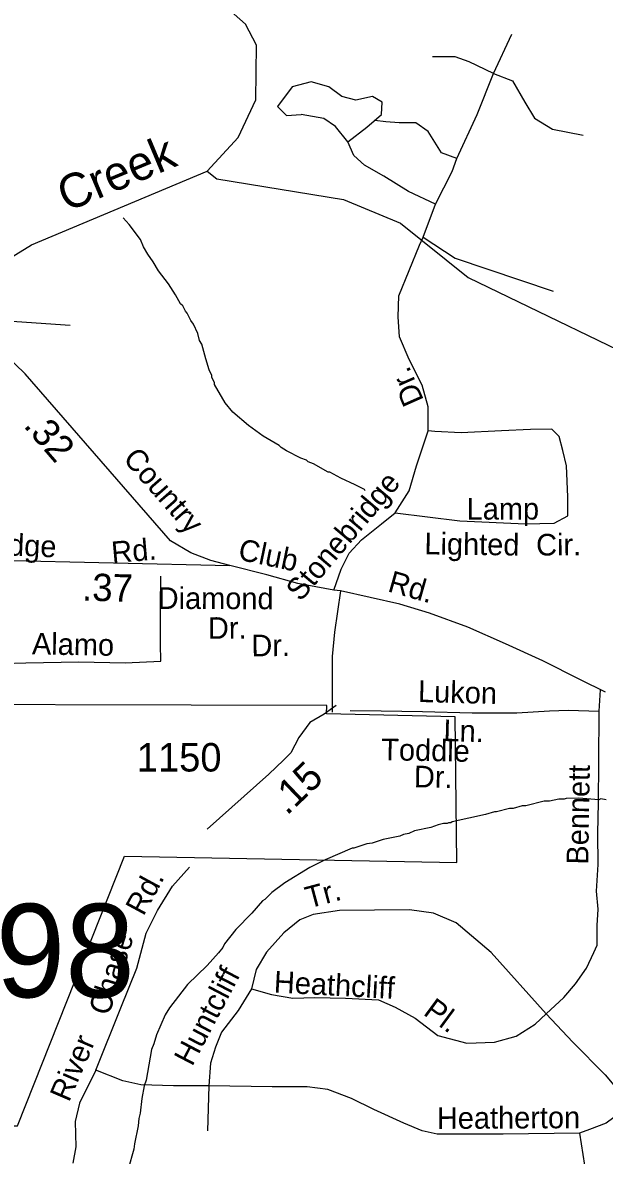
# Model space of a CAD drawing. Extents: x 1547597 to 1699558, y 810033 to 920809.
# Drawn here: x 1597107 to 1599658, y 851025 to 855999 of the extents above; entities that cross this region are included whole.
import ezdxf

# ---------------------------------------------------------------- set-up
doc = ezdxf.new("R2010")
doc.units = 0
for name, color, linetype in [('Exist Boundary Political City Limit New', 7, 'Continuous'), ('Exist Hydrographic Creek Single Shore', 7, 'Continuous'), ('Exist Hydrographic Creek Single Shore Label', 7, 'Continuous'), ('Exist Hydrographic Misc Water Feature', 7, 'Continuous'), ('Exist Road Non-System Type 51', 7, 'Continuous'), ('Exist Road Non-System Type 51 Label', 7, 'Continuous'), ('Exist Road Secondary Mileage Hundredths English Label', 7, 'Continuous'), ('Exist Road Secondary Structure Standard Bridge CELL', 7, 'Continuous'), ('Exist Road Secondary Structure Standard Bridge Number Label', 7, 'Continuous'), ('Exist Road Secondary Type 51 Attributed', 7, 'Continuous'), ('Exist Road Secondary Type 51 Label', 7, 'Continuous'), ('Exist Road Secondary Type 51 Number Label', 7, 'Continuous'), ('Map Preparation Boundary City Limit Buffer Line', 7, 'Continuous')]:
    doc.layers.add(name, color=color, linetype=linetype)

msp = doc.modelspace()

# ---------------------------------------------------------------- linework, layer by layer
at = {"layer": 'Exist Boundary Political City Limit New'}
msp.add_lwpolyline([(1598966.2, 848889), (1598696.7, 848933.6), (1598735.8, 849260.4), (1597051.5, 849266), (1596744.3, 849248.9), (1596741.6, 849203.1), (1596587.6, 849194.5), (1596790.6, 850274.8), (1596971.2, 851155.7), (1597083.9, 851155.7), (1597552.8, 852338.7), (1599010.8, 852311.7), (1599004, 852951.6), (1598440.1, 852963.6), (1598441.2, 853000.9), (1596057.5, 853006.4)], dxfattribs=at)
at = {"layer": 'Exist Hydrographic Creek Single Shore'}
for points in [[(1597916.6, 855346.8), (1598051.6, 855495), (1598128.7, 855660.9), (1598132.7, 855900.5), (1598083.7, 855993.4), (1597959.6, 856104.2), (1597769.6, 856200), (1597613.6, 856400.1), (1597549.6, 856634.5), (1597500.6, 856710.9), (1597454.7, 856961.4), (1597490.7, 857151.1), (1597755.1, 857446.8), (1598364.4, 858096.9), (1598493.9, 858519.8), (1598638.6, 858913.6)], [(1596005.6, 853287.9), (1596117.6, 853594.1), (1596743.8, 854808.1), (1596918.7, 854884.4), (1597145.7, 855024.3), (1597916.6, 855346.8)]]:
    msp.add_lwpolyline(points, dxfattribs=at)
at = {"layer": 'Exist Hydrographic Misc Water Feature'}
for points in [[(1597916.6, 855346.8), (1597957.7, 855313.1), (1598514.6, 855223), (1598763.6, 855119.5), (1599060.6, 854880.4), (1599980.6, 854435), (1600204.6, 854374.6), (1600804.6, 854382.2), (1601163.6, 854427.4), (1601549.7, 854580.4), (1602405.6, 854986.5), (1603296.7, 855565.9), (1603514.7, 855656.7), (1603614.6, 855661.2)], [(1598609.3, 853943), (1598605.4, 853949), (1598565.7, 853969.5), (1598502.2, 853998.5), (1598454.6, 854025.1), (1598446.6, 854025.2), (1598383.1, 854062.1), (1598359.3, 854070.4), (1598351.4, 854078.5), (1598327.5, 854086.9), (1598264, 854119.7), (1598240.1, 854134.1), (1598232.3, 854142.2), (1598160.9, 854183.2), (1598097.6, 854230.1), (1598028.4, 854289), (1597995, 854329.5), (1597948.1, 854410.1), (1597948.2, 854418.1), (1597936.5, 854442.2), (1597936.6, 854450.2), (1597925, 854474.4), (1597909.7, 854522.6), (1597892.6, 854586.9), (1597882.8, 854602.9), (1597875.2, 854635), (1597855.7, 854675.3), (1597844, 854691.5), (1597828.5, 854723.7), (1597820.6, 854731.8), (1597808.9, 854756), (1597799.1, 854764.1), (1597777.6, 854804.4), (1597746.3, 854852.8), (1597703.1, 854909.4), (1597679.6, 854949.7), (1597656, 854982), (1597636.5, 855014.3), (1597623, 855046.5), (1597573.9, 855113.2), (1597547.8, 855142.6)], [(1599666.3, 852586.5), (1599642.3, 852590.8), (1599634.3, 852586.9), (1599546.4, 852594.2), (1599490.4, 852593), (1599482.3, 852589.1), (1599458.4, 852589.4), (1599418.2, 852580), (1599394.3, 852580.3), (1599314.1, 852559.5), (1599298.1, 852559.7), (1599257.9, 852548.2), (1599242, 852548.4), (1599185.8, 852533.2), (1599175.8, 852533.4), (1599137.6, 852521.9), (1598991.3, 852489.9), (1598985.3, 852486), (1598975.2, 852486.1), (1598969.2, 852482.3), (1598953.2, 852482.5), (1598929.2, 852476.8), (1598897, 852465.3), (1598824.8, 852450.3), (1598800.7, 852438.6), (1598776.6, 852434.9), (1598760.5, 852427.2), (1598688.4, 852412.2), (1598640.2, 852396.8), (1598616.2, 852393.2), (1598560, 852374), (1598552, 852374.1), (1598433.4, 852323.7), (1598366.9, 852288.7), (1598256, 852222.2), (1598199.5, 852179.1), (1598169.1, 852149.5), (1598159, 852143.6), (1598112.3, 852088.3), (1598041.4, 852017.3), (1597992.5, 851954), (1597984.3, 851938.1), (1597966.1, 851914.4), (1597915.3, 851859.1), (1597830.2, 851776.3), (1597750.9, 851673.4), (1597732.4, 851641.7), (1597693.2, 851554.2), (1597682.7, 851514.4), (1597672.4, 851490.6), (1597648.5, 851354.9), (1597640.2, 851331), (1597629.5, 851275.2), (1597622.6, 851211.3), (1597616.2, 851187.4), (1597613.9, 851155.5), (1597596.8, 851075.7), (1597594.4, 851051.8), (1597569.3, 850964.1)]]:
    msp.add_lwpolyline(points, dxfattribs=at)
at = {"layer": 'Exist Road Non-System Type 51'}
msp.add_line((1599635.2, 852975.4), (1599641.8, 853069.4), dxfattribs=at)
for points in [[(1599172.4, 855776.7), (1599253, 855948.7)], [(1599172.4, 855776.7), (1599065, 855827.7), (1599003.2, 855849.3), (1598903.8, 855849.3)], [(1599011.3, 855403), (1599099.9, 855596.6), (1599172.4, 855776.7)], [(1599172.4, 855776.7), (1599255.7, 855744.4), (1599309.4, 855650.3), (1599352.4, 855580.4), (1599430.3, 855532.1), (1599564.6, 855505.2)], [(1598533.2, 855475.6), (1598616.4, 855540.1), (1598680.9, 855596.6), (1598683.6, 855650.3), (1598640.6, 855674.5), (1598568.1, 855658.4), (1598506.3, 855674.5), (1598449.9, 855717.5), (1598372, 855739), (1598288.7, 855717.5), (1598224.3, 855631.5), (1598264.6, 855591.2), (1598329, 855596.6)], [(1598533.2, 855475.6), (1598479.4, 855542.8), (1598428.4, 855577.8), (1598329, 855596.6)], [(1599011.3, 855403), (1598944.1, 855427.2), (1598885, 855521.3), (1598831.3, 855558.9), (1598758.8, 855558.9), (1598699.7, 855564.3), (1598651.3, 855569.7)], [(1598917.5, 855202.7), (1598799.1, 855257.9), (1598691.6, 855325.1), (1598605.7, 855373.5), (1598560, 855416.5), (1598533.2, 855475.6)], [(1598917.5, 855202.7), (1598990, 855345.1), (1599011.3, 855403)], [(1598863.7, 855057.5), (1598917.5, 855202.7)], [(1598885.3, 854206.8), (1598885.2, 854312.9), (1598858.4, 854407), (1598802, 854519.9), (1598759, 854619.4), (1598753.6, 854708.1), (1598756.3, 854799.5), (1598847.6, 855022.6), (1598863.7, 855057.5)], [(1598863.7, 855057.5), (1599003.2, 854964.9), (1599433, 854819.7)], [(1598740.3, 853846.6), (1599025, 853811.6), (1599312.4, 853798.2), (1599438.6, 853800.9), (1599497.7, 853833.1), (1599497.7, 853916.4), (1599492.4, 854053.5), (1599476.2, 854120.7), (1599460.1, 854182.6), (1599427.9, 854214.8), (1599333.9, 854212.1), (1599207.6, 854206.8), (1599030.4, 854198.7), (1598914.9, 854204.1), (1598885.3, 854206.8)], [(1598740.3, 853846.6), (1598802.1, 853943.3), (1598834.3, 854053.5), (1598885.3, 854206.8)], [(1598471.7, 853507.9), (1598503.9, 853599.3), (1598538.8, 853669.1), (1598592.6, 853728.3), (1598681.2, 853798.2), (1598740.3, 853846.6)], [(1597712.1, 853195.5), (1597711.4, 853271.5), (1597710.6, 853437.4), (1597712.9, 853569.4)], [(1598501, 853503.6), (1598474.1, 853323.1), (1598464.4, 853215.8)], [(1596622.8, 853179.5), (1596724.9, 853179.7), (1596916.6, 853182.2), (1597120.4, 853188.4), (1597352.4, 853192.1), (1597556.1, 853188.4), (1597712.1, 853195.5)], [(1598464.4, 853215.8), (1598464.4, 852971.8)], [(1598542.7, 852979.1), (1598679, 852977.9), (1598860.6, 852974.4), (1599078.2, 852968.4), (1599274.1, 852968.9), (1599417.5, 852976.7), (1599499.6, 852979.9), (1599635.2, 852975.4)], [(1599402.5, 851647.4), (1599480.5, 851718.2), (1599531.6, 851777.9), (1599579.3, 851847.3), (1599612.5, 851916.7), (1599626.7, 851948.6), (1599627, 852034.5), (1599630.5, 852106.3), (1599624.2, 852185.3), (1599631.5, 852302.4), (1599630.3, 852439.1), (1599632.7, 852574.9), (1599634, 852751.2), (1599635.2, 852975.4)], [(1597427.1, 851399), (1597536.8, 851673.7), (1597607.5, 851846.9), (1597648.9, 852000.6), (1597697.7, 852100.6), (1597763.5, 852208), (1597839.1, 852290.9)], [(1599402.5, 851647.4), (1599161.6, 851915.4), (1599008.1, 852047.1), (1598908.1, 852088.6), (1598803.3, 852103.2), (1598496.1, 852100.8), (1598381.6, 852083.7), (1598323.1, 852059.3), (1598252.4, 852003.2), (1598176.8, 851917.8), (1598130.5, 851842.2), (1598111, 851756.8)], [(1598111, 851756.8), (1598052.5, 851661.7), (1597979.4, 851566.5), (1597952.6, 851500.7), (1597930.6, 851429.9), (1597923.3, 851329.9)], [(1598111, 851756.8), (1598198.8, 851732.4), (1598291.4, 851715.3), (1598388.9, 851717.8), (1598523, 851715.3), (1598666.8, 851708), (1598739.9, 851676.3), (1598827.7, 851627.5), (1598927.6, 851551.9), (1599054.4, 851517.7), (1599176.3, 851522.6), (1599271.3, 851549.4), (1599354.2, 851600.7), (1599402.5, 851647.4)], [(1599402.5, 851647.4), (1599519.5, 851523), (1599662.1, 851378.5), (1599773.1, 851245.5)], [(1597427.1, 851399), (1597356.4, 851255), (1597336.9, 851174.5), (1597339.4, 851062.3), (1597327.2, 850991.6)], [(1597923.3, 851329.9), (1597768.4, 851330.7), (1597624.6, 851335.6), (1597546.6, 851352.6), (1597427.1, 851399)], [(1597923.3, 851329.9), (1597917.1, 851133.1)], [(1599548.9, 851123.5), (1599214.9, 851118.6), (1599054, 851118.6), (1598924.8, 851118.6), (1598859, 851133.3), (1598778.6, 851167.4), (1598646.9, 851226), (1598549.4, 851274.8), (1598444.6, 851313.8), (1598354.4, 851326), (1598200.9, 851326), (1597923.3, 851329.9)], [(1599773.1, 851245.5), (1599665.9, 851167.4), (1599592.8, 851138.2), (1599548.9, 851123.5)], [(1599548.9, 851123.5), (1599578.1, 850935.7)]]:
    msp.add_lwpolyline(points, dxfattribs=at)
at = {"layer": 'Exist Road Secondary Structure Standard Bridge CELL'}
msp.add_line((1597039, 854689.6), (1597314.3, 854671.5), dxfattribs=at)
at = {"layer": 'Exist Road Secondary Type 51 Attributed'}
for points in [[(1598015.9, 853615.1), (1597931.9, 853636.9), (1597844.8, 853671.2), (1597754.5, 853724.1), (1597117, 854457.7), (1596942.9, 854624), (1596772.6, 854822.1)], [(1596103.5, 852639.6), (1596169.3, 852683.2), (1596283.5, 852774.6), (1596371.6, 852874.3), (1596431, 853004.5), (1596556.7, 853256.2), (1596616.2, 853394.7), (1596670.6, 853490.5), (1596699.1, 853529.3), (1596739.2, 853565.6), (1596770.3, 853596.7), (1596827.5, 853623.6), (1596994, 853639.4), (1598015.9, 853615.1)], [(1599663.7, 853059.6), (1599554, 853113.3), (1599388.3, 853196.3), (1599224.9, 853271.9), (1599059.2, 853345.1), (1598891, 853406.1), (1598761.8, 853445.1), (1598501, 853503.6), (1598471.7, 853507.9), (1598313.7, 853536.2), (1598177.8, 853574.6), (1598015.9, 853615.1)], [(1598481.3, 853000.5), (1598428.7, 852963), (1598366.1, 852926.1), (1598317.8, 852860.7), (1598283.1, 852793.5), (1598251.3, 852761), (1598186.2, 852698.6), (1597915.4, 852458.3)]]:
    msp.add_lwpolyline(points, dxfattribs=at)
at = {"layer": 'Map Preparation Boundary City Limit Buffer Line'}
msp.add_lwpolyline([(1598966.2, 848889), (1598696.7, 848933.6), (1598735.8, 849260.4), (1597051.5, 849266), (1596744.3, 849248.9), (1596741.6, 849203.1), (1596587.6, 849194.5), (1596790.6, 850274.8), (1596971.2, 851155.7), (1597083.9, 851155.7), (1597552.8, 852338.7), (1599010.8, 852311.7), (1599004, 852951.6), (1598440.1, 852963.6), (1598441.2, 853000.9), (1596057.5, 853006.4)], dxfattribs=at)

# ---------------------------------------------------------------- texts
at = {"layer": 'Exist Hydrographic Creek Single Shore Label'}
msp.add_text('Creek', height=150, rotation=22.6956, dxfattribs=at).set_placement((1597298.9, 855166.7))
at = {"layer": 'Exist Road Non-System Type 51 Label'}
for s, rotation, p in [('Dr.', 113.9453, (1598867.8, 854341.9)), ('Stonebridge', 49.7214, (1598325.8, 853453.6)), ('Lamp', 0.0231, (1599054.2, 853817.2)), ('Lighted', 359.2625, (1598868.5, 853664.6)), ('Cir.', 0.3014, (1599359.1, 853659.1)), ('Diamond', 359.8157, (1597698.9, 853425)), ('Dr.', 0.2889, (1597919.5, 853293.5)), ('Alamo', 358.9496, (1597146.8, 853225.5)), ('Dr.', 0.6539, (1598110.4, 853216.2)), ('Lukon', 358.4169, (1598840, 853016.4)), ('Ln.', 358.4169, (1598951.7, 852844.7)), ('Toddle', 358.901, (1598678.9, 852760.8)), ('Bennett', 89.0064, (1599587.2, 852301.6)), ('Dr.', 358.901, (1598822.2, 852641.8)), ('Rd.', 61.5659, (1597636.6, 852072.6)), ('Tr.', 14.9233, (1598361, 852109.1)), ('Chase', 72.4853, (1597484.7, 851634.7)), ('Huntcliff', 62.3659, (1597850.3, 851412.4)), ('Heathcliff', 356.9166, (1598206.8, 851740.8)), ('Pl.', 323.6373, (1598859.6, 851645.7)), ('River', 66.6582, (1597309.7, 851255.5)), ('Heatherton', 0.3089, (1598923.8, 851141.4))]:
    msp.add_text(s, height=95, rotation=rotation, dxfattribs=at).set_placement(p)
at = {"layer": 'Exist Road Secondary Mileage Hundredths English Label'}
for s, height, rotation, p in [('.32', 120, 310.8176, (1597107, 854228)), ('.37', 120, 358.6377, (1597366.1, 853461.3)), ('.15', 125, 43.7546, (1598265.4, 852514.9))]:
    msp.add_text(s, height=height, rotation=rotation, dxfattribs=at).set_placement(p)
at = {"layer": 'Exist Road Secondary Structure Standard Bridge Number Label'}
msp.add_text('98', height=410.1, dxfattribs=at).set_placement((1596988.3, 851719.5))
at = {"layer": 'Exist Road Secondary Type 51 Label'}
for s, rotation, p in [('Country', 311.2256, (1597543, 854081.7)), ('Bridge', 357.516, (1596886.2, 853666.8)), ('Rd.', 5.006, (1597499.7, 853625.1)), ('Club', 348.2303, (1598047.3, 853642)), ('Rd.', 344.1454, (1598703.6, 853502.9))]:
    msp.add_text(s, height=95, rotation=rotation, dxfattribs=at).set_placement(p)
at = {"layer": 'Exist Road Secondary Type 51 Number Label'}
msp.add_text('1150', height=125, dxfattribs=at).set_placement((1597607.1, 852710.9))

doc.saveas('drawing.dxf')
